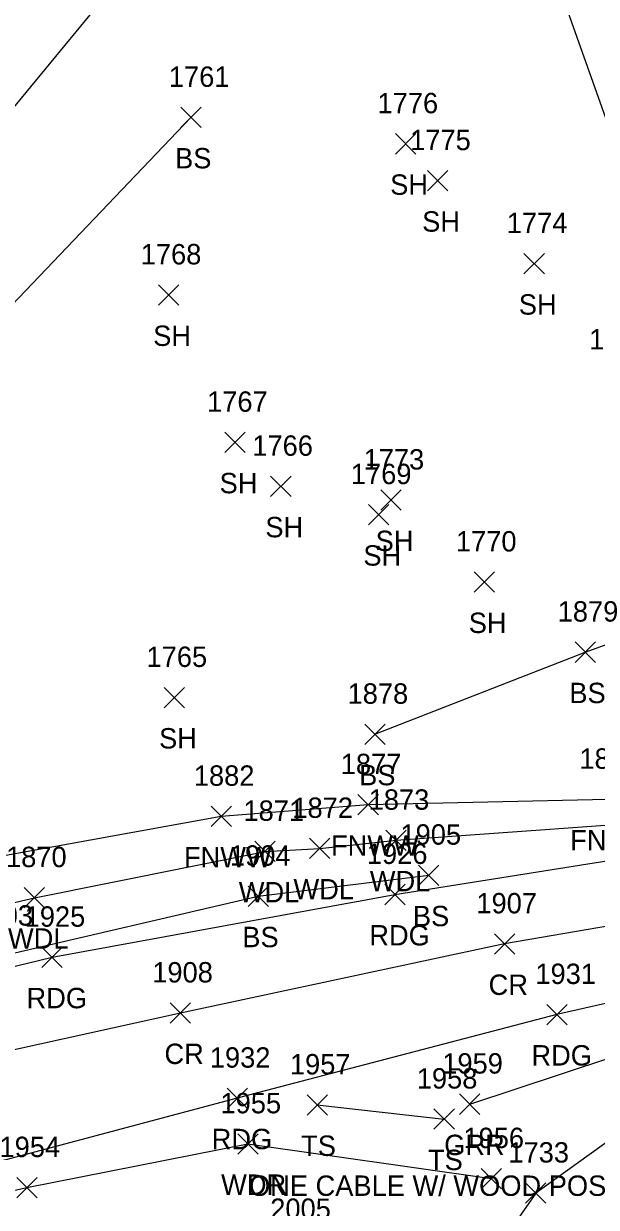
# Model space of a CAD drawing. Extents: x 1621633 to 1624015, y 417863 to 420979.
# Drawn here: x 1621891.2 to 1621947.4, y 418067.9 to 418184 of the extents above; entities that cross this region are included whole.
import ezdxf

# ---------------------------------------------------------------- set-up
doc = ezdxf.new("R2010")
doc.units = 0
for name, color, linetype in [('L_A', 7, 'Continuous'), ('L_I', 7, 'Continuous'), ('L_TIC', 7, 'Continuous'), ('LAWA', 7, 'Continuous'), ('LELB', 7, 'Continuous'), ('LFNC', 7, 'Continuous'), ('M_I', 7, 'Continuous'), ('P_A', 7, 'Continuous'), ('P_I', 7, 'Continuous'), ('P_TIC', 7, 'Continuous'), ('PEU', 7, 'Continuous'), ('PRC', 7, 'Continuous'), ('R_A', 7, 'Continuous'), ('R_C', 7, 'Continuous'), ('R_I', 7, 'Continuous'), ('R_TIC', 7, 'Continuous'), ('RGR', 7, 'Continuous')]:
    doc.layers.add(name, color=color, linetype=linetype)

msp = doc.modelspace()

# ---------------------------------------------------------------- linework, layer by layer
at = {"layer": 'L_TIC'}
for points in [[(1621906.66, 418173.83), (1621908.66, 418175.83)], [(1621908.66, 418173.83), (1621906.66, 418175.83)], [(1621927.72, 418171.24), (1621929.72, 418173.24)], [(1621929.72, 418171.24), (1621927.72, 418173.24)], [(1621930.86, 418167.62), (1621932.86, 418169.62)], [(1621932.86, 418167.62), (1621930.86, 418169.62)], [(1621940.34, 418159.48), (1621942.34, 418161.48)], [(1621942.34, 418159.48), (1621940.34, 418161.48)], [(1621904.47, 418156.41), (1621906.47, 418158.41)], [(1621906.47, 418156.41), (1621904.47, 418158.41)], [(1621910.98, 418141.95), (1621912.98, 418143.95)], [(1621912.98, 418141.95), (1621910.98, 418143.95)], [(1621915.48, 418137.63), (1621917.48, 418139.63)], [(1621917.48, 418137.63), (1621915.48, 418139.63)], [(1621926.3, 418136.28), (1621928.3, 418138.28)], [(1621928.3, 418136.28), (1621926.3, 418138.28)], [(1621925.09, 418134.85), (1621927.09, 418136.85)], [(1621927.09, 418134.85), (1621925.09, 418136.85)], [(1621935.44, 418128.24), (1621937.44, 418130.24)], [(1621937.44, 418128.24), (1621935.44, 418130.24)], [(1621945.35, 418121.36), (1621947.35, 418123.36)], [(1621947.35, 418121.36), (1621945.35, 418123.36)], [(1621905.04, 418116.91), (1621907.04, 418118.91)], [(1621907.04, 418116.91), (1621905.04, 418118.91)], [(1621924.72, 418113.3), (1621926.72, 418115.3)], [(1621926.72, 418113.3), (1621924.72, 418115.3)], [(1621924.05, 418106.39), (1621926.05, 418108.39)], [(1621926.05, 418106.39), (1621924.05, 418108.39)], [(1621909.63, 418105.25), (1621911.63, 418107.25)], [(1621911.63, 418105.25), (1621909.63, 418107.25)], [(1621926.79, 418102.9), (1621928.79, 418104.9)], [(1621928.79, 418102.9), (1621926.79, 418104.9)], [(1621913.93, 418101.81), (1621915.93, 418103.81)], [(1621915.93, 418101.81), (1621913.93, 418103.81)], [(1621919.3, 418102.1), (1621921.3, 418104.1)], [(1621921.3, 418102.1), (1621919.3, 418104.1)], [(1621930, 418099.47), (1621932, 418101.47)], [(1621932, 418099.47), (1621930, 418101.47)], [(1621891.29, 418097.27), (1621893.29, 418099.27)], [(1621893.29, 418097.27), (1621891.29, 418099.27)], [(1621913.26, 418097.41), (1621915.26, 418099.41)], [(1621915.26, 418097.41), (1621913.26, 418099.41)], [(1621919.06, 418076.93), (1621921.06, 418078.93)], [(1621921.06, 418076.93), (1621919.06, 418078.93)], [(1621931.51, 418075.54), (1621933.51, 418077.54)], [(1621933.51, 418075.54), (1621931.51, 418077.54)], [(1621912.25, 418073.11), (1621914.25, 418075.11)], [(1621914.25, 418073.11), (1621912.25, 418075.11)], [(1621936.15, 418069.7), (1621938.15, 418071.7)], [(1621938.15, 418069.7), (1621936.15, 418071.7)], [(1621890.56, 418068.82), (1621892.56, 418070.82)], [(1621892.56, 418068.82), (1621890.56, 418070.82)], [(1621940.5, 418068.28), (1621942.5, 418070.28)], [(1621942.5, 418068.28), (1621940.5, 418070.28)]]:
    msp.add_lwpolyline(points, dxfattribs=at)
at = {"layer": 'LAWA'}
for points in [[(1621956.58, 418284.61), (1621944.79, 418263.74), (1621937.99, 418240.81), (1621923.64, 418212.08), (1621903.11, 418191.44), (1621882.69, 418166.67), (1621873.44, 418154.29), (1621850.99, 418135.57), (1621826.17, 418116.06), (1621804.72, 418096.14), (1621776.82, 418074.39), (1621781.78, 418070.72), (1621808.71, 418078.7), (1621829.62, 418083.56), (1621862.33, 418091.33), (1621892.29, 418098.27), (1621914.93, 418102.81), (1621920.3, 418103.1), (1621927.79, 418103.9), (1621958.83, 418106.15)], [(1621964.88, 418112.57), (1621960.51, 418127.09), (1621958.47, 418132.3), (1621952.2, 418163.99), (1621942.42, 418191.54), (1621933.84, 418203.58)], [(1621679.19, 417971.6), (1621702.48, 417990.45), (1621715.01, 418000.48), (1621736.64, 418013.96), (1621752.88, 418023.2), (1621756.92, 418025.88), (1621771.11, 418032.08), (1621799.59, 418044.88), (1621821.8, 418051.6), (1621846.96, 418058.28), (1621864.11, 418063.69), (1621891.56, 418069.82), (1621913.25, 418074.11), (1621937.15, 418070.7)]]:
    msp.add_lwpolyline(points, dxfattribs=at)
at = {"layer": 'LELB'}
for points in [[(1621837.73, 418093.38), (1621852.21, 418117.02), (1621868.22, 418131.62), (1621888.03, 418154.29), (1621907.66, 418174.83)], [(1621925.72, 418114.3), (1621946.35, 418122.36), (1621954.5, 418125.31)], [(1621664.03, 417989.43), (1621687.49, 418007.66), (1621711.94, 418024.27), (1621730.31, 418035.53), (1621752.55, 418048.38), (1621767.69, 418055), (1621798.3, 418066.25), (1621826.91, 418075.93), (1621858.25, 418085.3), (1621888.98, 418092.53), (1621914.26, 418098.41), (1621931, 418100.47)], [(1621962.89, 418084.64), (1621941.5, 418069.28), (1621934.53, 418059.29), (1621911.15, 418049.77), (1621884.84, 418045.66), (1621868.89, 418041.42), (1621850.26, 418038.2), (1621830.71, 418031.9), (1621803.35, 418026.98), (1621784.31, 418024.31)], [(1621920.06, 418077.93), (1621932.51, 418076.54)]]:
    msp.add_lwpolyline(points, dxfattribs=at)
at = {"layer": 'LFNC'}
msp.add_lwpolyline([(1621964.2, 418111.07), (1621948.53, 418107.92), (1621925.05, 418107.39), (1621910.63, 418106.25), (1621880.44, 418100.76), (1621858.02, 418096.03), (1621836.43, 418089.43), (1621812.81, 418084.09), (1621788.07, 418077.58)], dxfattribs=at)
at = {"layer": 'P_TIC'}
for points in [[(1621926.67, 418097.58), (1621928.67, 418099.58)], [(1621928.67, 418097.58), (1621926.67, 418099.58)], [(1621937.44, 418092.73), (1621939.44, 418094.73)], [(1621939.44, 418092.73), (1621937.44, 418094.73)], [(1621893.03, 418091.42), (1621895.03, 418093.42)], [(1621895.03, 418091.42), (1621893.03, 418093.42)], [(1621905.63, 418085.95), (1621907.63, 418087.95)], [(1621907.63, 418085.95), (1621905.63, 418087.95)], [(1621942.58, 418085.8), (1621944.58, 418087.8)], [(1621944.58, 418085.8), (1621942.58, 418087.8)], [(1621911.2, 418077.59), (1621913.2, 418079.59)], [(1621913.2, 418077.59), (1621911.2, 418079.59)]]:
    msp.add_lwpolyline(points, dxfattribs=at)
at = {"layer": 'PEU'}
msp.add_lwpolyline([(1621862.24, 418084.7), (1621894.03, 418092.42), (1621927.67, 418098.58), (1621959.16, 418103.59), (1621971.71, 418106.23), (1621972.71, 418099.54), (1621973.23, 418093.52), (1621943.58, 418086.8), (1621912.2, 418078.59), (1621881, 418070.29)], dxfattribs=at)
at = {"layer": 'PRC'}
msp.add_lwpolyline([(1621971.07, 418099.34), (1621938.44, 418093.73), (1621906.63, 418086.95), (1621874.87, 418079.94), (1621842.52, 418071.19), (1621811.53, 418061.42), (1621780.51, 418050.11), (1621750.95, 418035.3), (1621723.04, 418018.53), (1621696.18, 418000.53), (1621670.93, 417981.57)], dxfattribs=at)
at = {"layer": 'R_TIC'}
for points in [[(1621934.02, 418077.01), (1621936.02, 418079.01)], [(1621936.02, 418077.01), (1621934.02, 418079.01)]]:
    msp.add_lwpolyline(points, dxfattribs=at)
at = {"layer": 'RGR'}
msp.add_lwpolyline([(1621935.02, 418078.01), (1621953.42, 418084.09), (1621973.07, 418092.58)], dxfattribs=at)

# ---------------------------------------------------------------- texts
at = {"layer": 'L_A'}
for s, p in [('BS', (1621906.1, 418169.83)), ('SH', (1621927.21, 418167.24)), ('SH', (1621930.35, 418163.62)), ('SH', (1621939.83, 418155.48)), ('SH', (1621903.95, 418152.41)), ('SH', (1621910.47, 418137.95)), ('SH', (1621914.96, 418133.63)), ('SH', (1621925.78, 418132.28)), ('SH', (1621924.58, 418130.85)), ('SH', (1621934.92, 418124.24)), ('BS', (1621944.79, 418117.36)), ('SH', (1621904.53, 418112.91)), ('BS', (1621924.16, 418109.3)), ('FNWW', (1621921.4, 418102.39)), ('FNWW', (1621944.88, 418102.92)), ('FNWW', (1621906.97, 418101.25)), ('WDL', (1621925.21, 418098.9)), ('WDL', (1621912.35, 418097.81)), ('WDL', (1621917.72, 418098.1)), ('BS', (1621929.44, 418095.47)), ('WDL', (1621889.7, 418093.27)), ('BS', (1621912.7, 418093.41)), ('TS', (1621918.47, 418072.93)), ('TS', (1621930.92, 418071.54)), ('WDR', (1621910.62, 418069.11))]:
    msp.add_text(s, height=2, dxfattribs=at).set_placement(p)
at = {"layer": 'L_I'}
for s, p in [('1761', (1621905.49, 418177.83)), ('1776', (1621925.97, 418175.24)), ('1775', (1621929.17, 418171.62)), ('1774', (1621938.65, 418163.48)), ('1768', (1621902.73, 418160.41)), ('1772', (1621946.74, 418152.07)), ('1767', (1621909.24, 418145.95)), ('1766', (1621913.68, 418141.63)), ('1773', (1621924.6, 418140.28)), ('1769', (1621923.35, 418138.85)), ('1770', (1621933.66, 418132.24)), ('1879', (1621943.65, 418125.36)), ('1765', (1621903.3, 418120.91)), ('1878', (1621923.03, 418117.3)), ('1877', (1621922.36, 418110.39)), ('1876', (1621945.78, 418110.92)), ('1882', (1621907.94, 418109.25)), ('1873', (1621925.1, 418106.9)), ('1871', (1621912.81, 418105.81)), ('1872', (1621917.61, 418106.1)), ('1905', (1621928.22, 418103.47)), ('1870', (1621889.51, 418101.27)), ('1904', (1621911.48, 418101.41)), ('1903', (1621886.21, 418095.53)), ('1957', (1621917.37, 418080.93)), ('1958', (1621929.82, 418079.54)), ('1955', (1621910.56, 418077.11)), ('1956', (1621934.4, 418073.7)), ('1954', (1621888.87, 418072.82)), ('1733', (1621938.81, 418072.28))]:
    msp.add_text(s, height=2, dxfattribs=at).set_placement(p)
at = {"layer": 'M_I'}
msp.add_text('2005', height=2, dxfattribs=at).set_placement((1621915.44, 418066.75))
at = {"layer": 'P_A'}
for s, p in [('RDG', (1621925.16, 418093.58)), ('CR', (1621936.87, 418088.73)), ('RDG', (1621891.52, 418087.42)), ('CR', (1621905.06, 418081.95)), ('RDG', (1621941.07, 418081.8)), ('RDG', (1621909.69, 418073.59))]:
    msp.add_text(s, height=2, dxfattribs=at).set_placement(p)
at = {"layer": 'P_I'}
for s, p in [('1926', (1621924.92, 418101.58)), ('1907', (1621935.67, 418096.73)), ('1925', (1621891.34, 418095.42)), ('1908', (1621903.86, 418089.95)), ('1931', (1621941.46, 418089.8)), ('1932', (1621909.51, 418081.59))]:
    msp.add_text(s, height=2, dxfattribs=at).set_placement(p)
at = {"layer": 'R_A'}
msp.add_text('GRR', height=2, dxfattribs=at).set_placement((1621932.51, 418073.01))
at = {"layer": 'R_C'}
msp.add_text('ONE CABLE W/ WOOD POSTS', height=2, dxfattribs=at).set_placement((1621913.35, 418069.01))
at = {"layer": 'R_I'}
msp.add_text('1959', height=2, dxfattribs=at).set_placement((1621932.32, 418081.01))

doc.saveas('drawing.dxf')
